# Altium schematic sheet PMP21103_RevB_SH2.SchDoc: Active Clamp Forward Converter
size 431 x 279 mm; Date: Not shown in title block; ApprovedBy: Not shown in title block; CheckedBy: Not shown in title block; Author: Not shown in title block; CompanyName: Not shown in title block; Engineer: Not shown in title block; Organization: Not shown in title block; Address1: Not shown in title block; Address2: Not shown in title block; Address3: Not shown in title block; Address4: Not shown in title block; DocumentNumber: 2; Revision: Use project parameter SCH_Rev; SheetNumber: 2; SheetTotal: 3; PageSetup: Record=PageOptions¦CenterHorizontal=True¦CenterVertical=True¦PrintScale=1.00¦XCorrection=1.00¦YCorrection=1.00¦PrintKind=0¦BorderSize=5000000¦LeftOffset=0¦BottomOffset=0¦Orientation=2¦PaperLength=1000¦PaperWidth=1000¦Scale=100¦PaperSource=15¦PrintQuality=600¦MediaType=1¦DitherType=10¦PaperKind=Letter¦PrintScaleMode=1
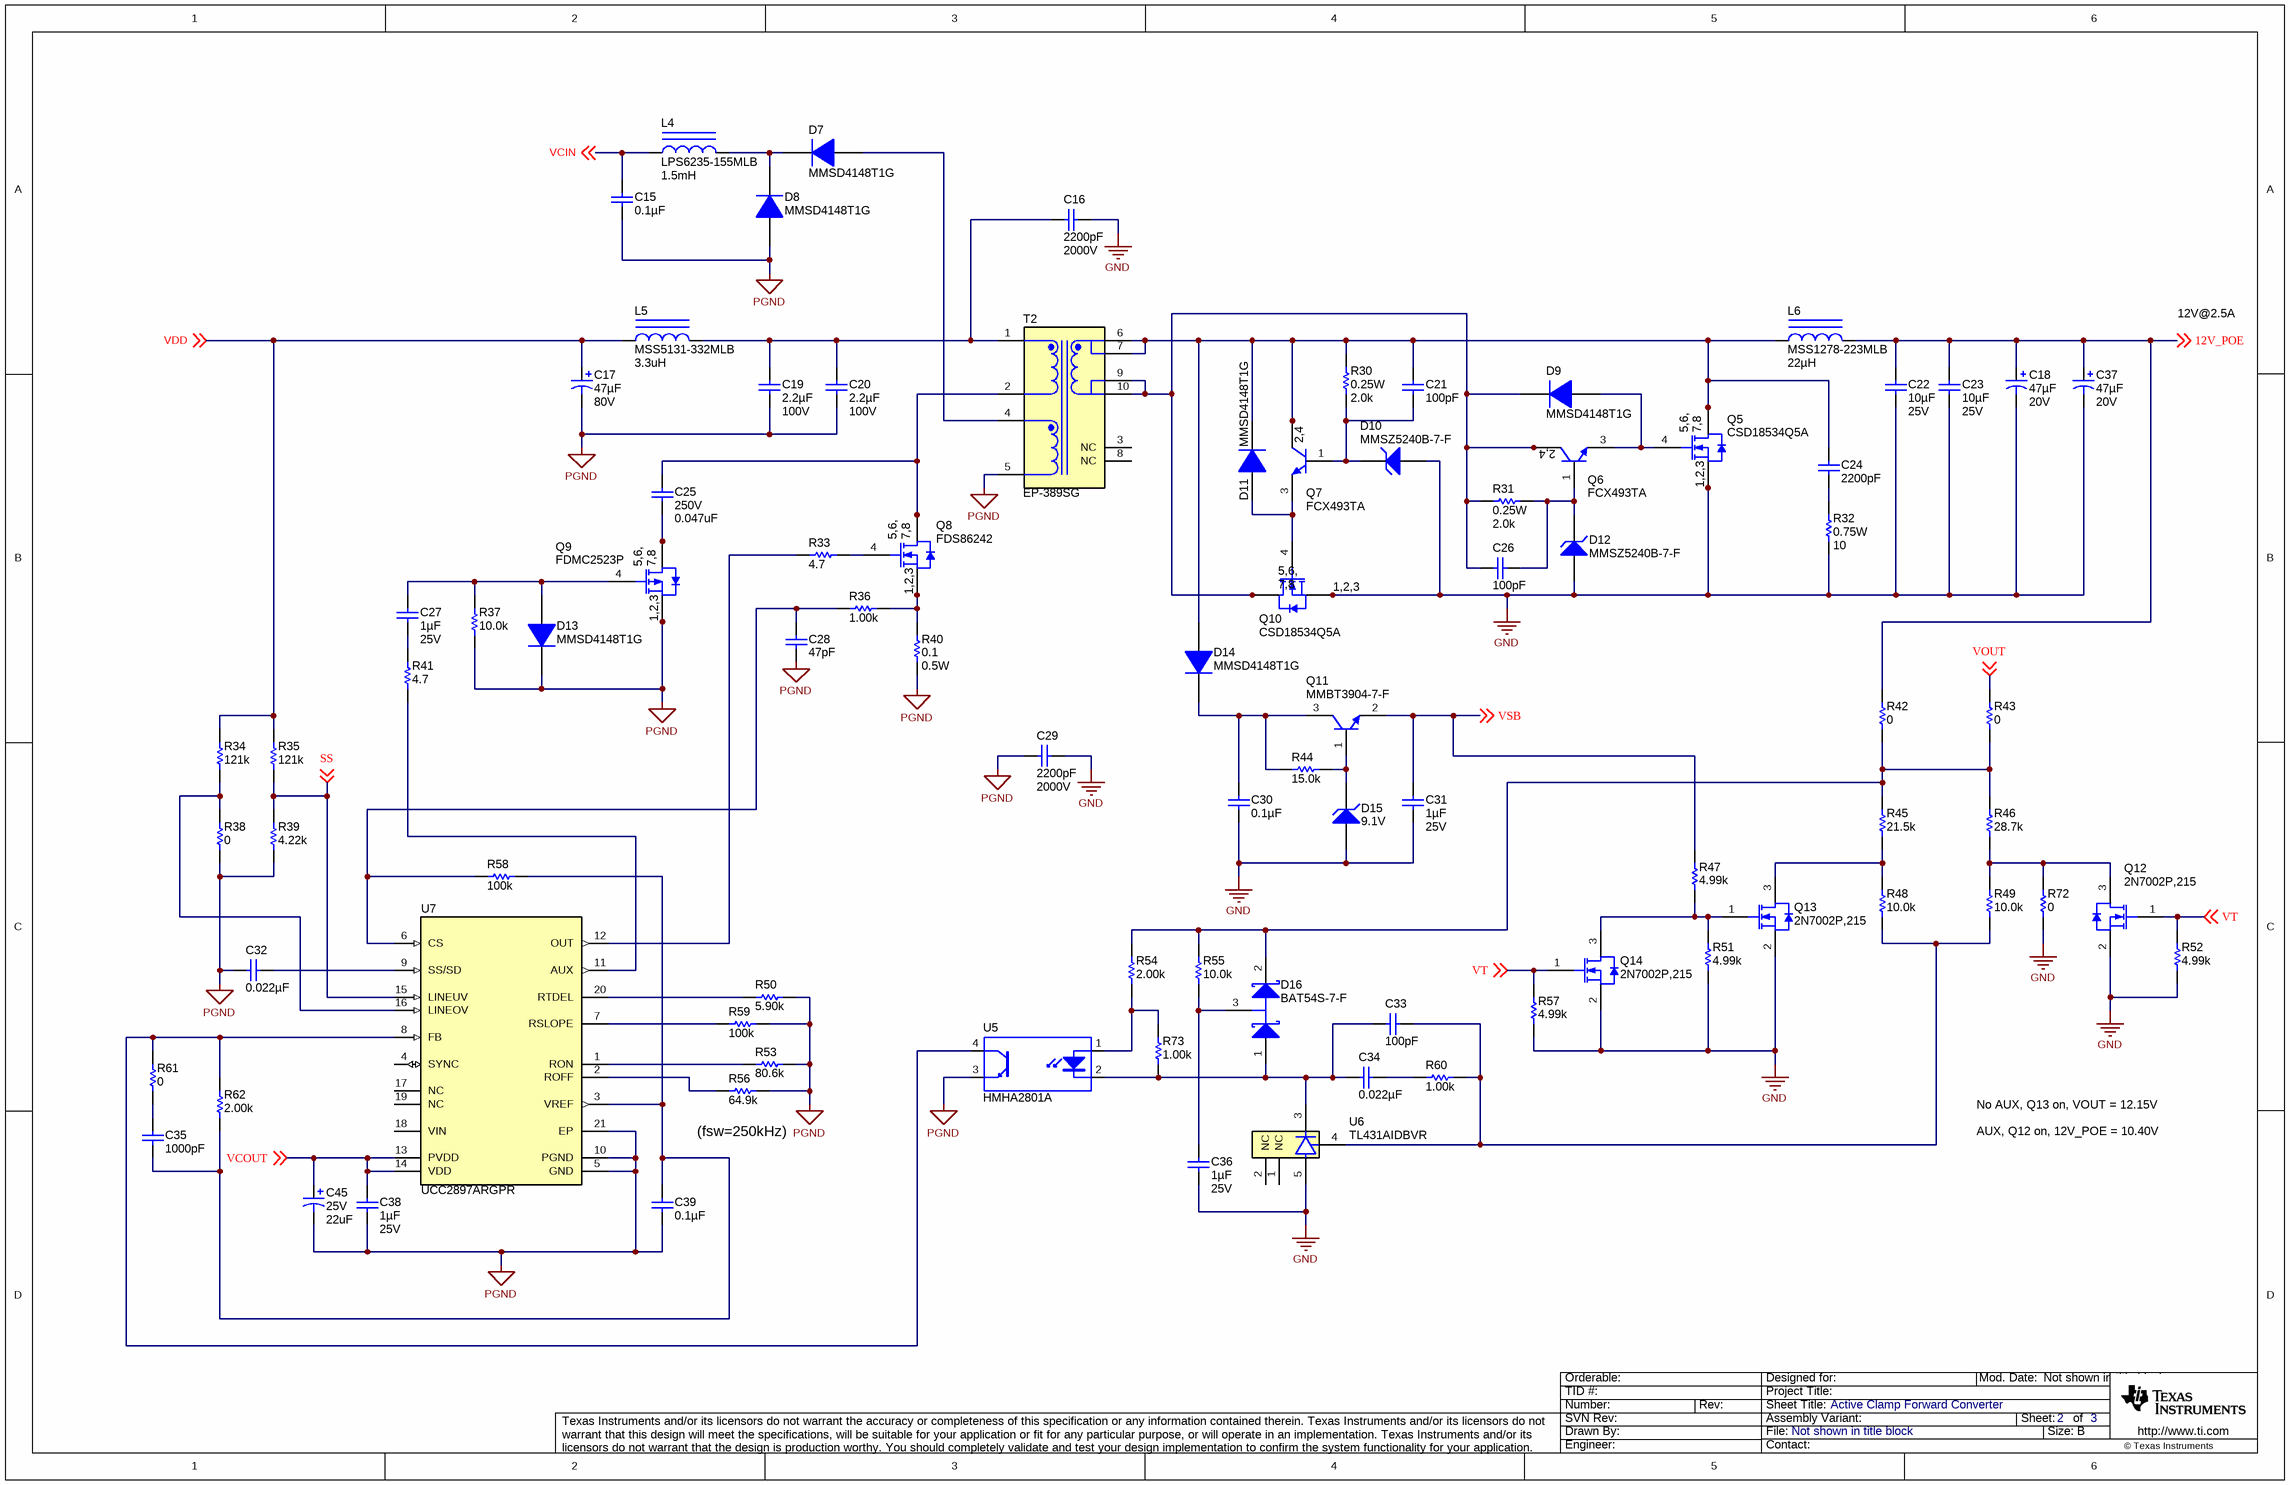
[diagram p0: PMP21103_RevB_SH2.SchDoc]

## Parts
C15  ValueDisplayed: 0.1µF  [0603]  (hidden comment: C1608X7R1H104K080AA)
C16  ValueDisplayed: 2200pF  Value2: 2000V  [1812]  (hidden comment: C4532X7R3D222K130KA)
C17  ValueDisplayed: 47µF  Value2: 80V  [SM_RADIAL_G]  (hidden comment: EEE-FK1K470P)
C18  ValueDisplayed: 47µF  Value2: 20V  [SM_RADIAL_8MM]  (hidden comment: 20SVP47M)
C19  ValueDisplayed: 2.2µF  Value2: 100V  [1210_270]  (hidden comment: GRM32ER72A225KA35L)
C20  ValueDisplayed: 2.2µF  Value2: 100V  [1210_270]  (hidden comment: GRM32ER72A225KA35L)
C21  ValueDisplayed: 100pF  [0603L]  (hidden comment: C1608C0G1H101J080AE)
C22  ValueDisplayed: 10µF  Value2: 25V  [1210_220]  (hidden comment: 885012209028)
C23  ValueDisplayed: 10µF  Value2: 25V  [1210_220]  (hidden comment: 885012209028)
C24  ValueDisplayed: 2200pF  [0603L]  (hidden comment: GRM188R71H222KA01D)
C25  VDC_V: 250V  ValueDisplayed: 0.047uF  [1206_180]  (hidden comment: GRM31CR72E473KW03L)
C26  ValueDisplayed: 100pF  [0603L]  (hidden comment: C1608C0G1H101J080AE)
C27  ValueDisplayed: 1µF  Value2: 25V  [0805L]  (hidden comment: GRM21BR71E105KA99L)
C28  ValueDisplayed: 47pF  [0603L]  (hidden comment: GRM1885C1H470JA01D)
C29  ValueDisplayed: 2200pF  Value2: 2000V  [1812]  (hidden comment: C4532X7R3D222K130KA)
C30  ValueDisplayed: 0.1µF  [0603L]  (hidden comment: C1608X7R1H104K080AA)
C31  ValueDisplayed: 1µF  Value2: 25V  [0805_HV]  (hidden comment: GRM21BR71E105KA99L)
C32  ValueDisplayed: 0.022µF  [0603L]  (hidden comment: GRM188R71H223KA01D)
C33  ValueDisplayed: 100pF  [0603L]  (hidden comment: C1608C0G1H101J080AE)
C34  ValueDisplayed: 0.022µF  [0603L]  (hidden comment: GRM188R71H223KA01D)
C35  ValueDisplayed: 1000pF  [0603]  (hidden comment: GRM188R71H102KA01D)
C36  ValueDisplayed: 1µF  Value2: 25V  [0805_HV]  (hidden comment: GRM21BR71E105KA99L)
C37  ValueDisplayed: 47µF  Value2: 20V  [SM_RADIAL_8MM]  (hidden comment: 20SVP47M)
C38  ValueDisplayed: 1µF  Value2: 25V  [0805L]  (hidden comment: GRM21BR71E105KA99L)
C39  ValueDisplayed: 0.1µF  [0603L]  (hidden comment: C1608X7R1H104K080AA)
C45  VDC_V: 25V  ValueDisplayed: 22uF  [SM_RADIAL_C]  (hidden comment: EEE-FK1E220R)
D7  MMSD4148T1G  [SOD-123]
D8  MMSD4148T1G  [SOD-123]
D9  MMSD4148T1G  [SOD-123]
D10  MMSZ5240B-7-F  [SOD-123]
D11  MMSD4148T1G  [SOD-123]
D12  MMSZ5240B-7-F  [SOD-123]
D13  MMSD4148T1G  [SOD-123]
D14  MMSD4148T1G  [SOD-123]
D15  value 9.1V  [SOD-523]  (hidden comment: BZT52C9V1T-7)
D16  BAT54S-7-F  [SOT-23]
L4  LPS6235-155MLB  ValueDisplayed: 1.5mH  [LPS6235]
L5  MSS5131-332MLB  value 3.3uH  [MSS5131]
L6  MSS1278-223MLB  ValueDisplayed: 22µH  [MSS1278]
Q5  CSD18534Q5A  [DQJ0008A]
Q6  FCX493TA  [SOT-89-3]
Q7  FCX493TA  [SOT-89-3]
Q8  FDS86242  [SOIC-8]
Q9  FDMC2523P  [MLP08S]
Q10  CSD18534Q5A  [DQJ0008A]
Q11  MMBT3904-7-F  [SOT-23]
Q12  2N7002P,215  [SOT-23]
Q13  2N7002P,215  [SOT-23]
Q14  2N7002P,215  [SOT-23]
R30  Value2: 0.25W  ValueDisplayed: 2.0k  [1206L]  (hidden comment: CRCW12062K00JNEA)
R31  Value2: 0.25W  ValueDisplayed: 2.0k  [1206L]  (hidden comment: CRCW12062K00JNEA)
R32  Value2: 0.75W  ValueDisplayed: 10  [2010L]  (hidden comment: CRCW201010R0JNEF)
R33  ValueDisplayed: 4.7  [0603L]  (hidden comment: CRCW06034R70JNEA)
R34  ValueDisplayed: 121k  [0603L]  (hidden comment: CRCW0603121KFKEA)
R35  ValueDisplayed: 121k  [0603L]  (hidden comment: CRCW0603121KFKEA)
R36  ValueDisplayed: 1.00k  [0603]  (hidden comment: CRCW06031K00FKEA)
R37  ValueDisplayed: 10.0k  [0603L]  (hidden comment: CRCW060310K0FKEA)
R38  ValueDisplayed: 0  [0603L]  (hidden comment: CRCW06030000Z0EA)
R39  ValueDisplayed: 4.22k  [0603L]  (hidden comment: CRCW06034K22FKEA)
R40  value 0.1  Value2: 0.5W  [2010L]  (hidden comment: ERJ-L1DKF10CU)
R41  ValueDisplayed: 4.7  [0603L]  (hidden comment: CRCW06034R70JNEA)
R42  ValueDisplayed: 0  [0603L]  (hidden comment: CRCW06030000Z0EA)
R43  ValueDisplayed: 0  [0603L]  (hidden comment: CRCW06030000Z0EA)
R44  ValueDisplayed: 15.0k  [0603]  (hidden comment: CRCW060315K0FKEA)
R45  ValueDisplayed: 21.5k  [0603]  (hidden comment: CRCW060321K5FKEA)
R46  ValueDisplayed: 28.7k  [0603L]  (hidden comment: CRCW060328K7FKEA)
R47  ValueDisplayed: 4.99k  [0603L]  (hidden comment: CRCW06034K99FKEA)
R48  ValueDisplayed: 10.0k  [0603L]  (hidden comment: CRCW060310K0FKEA)
R49  ValueDisplayed: 10.0k  [0603L]  (hidden comment: CRCW060310K0FKEA)
R50  ValueDisplayed: 5.90k  [0603L]  (hidden comment: CRCW06035K90FKEA)
R51  ValueDisplayed: 4.99k  [0603L]  (hidden comment: CRCW06034K99FKEA)
R52  ValueDisplayed: 4.99k  [0603L]  (hidden comment: CRCW06034K99FKEA)
R53  ValueDisplayed: 80.6k  [0603]  (hidden comment: CRCW060380K6FKEA)
R54  ValueDisplayed: 2.00k  [0603L]  (hidden comment: CRCW06032K00FKEA)
R55  ValueDisplayed: 10.0k  [0603L]  (hidden comment: CRCW060310K0FKEA)
R56  ValueDisplayed: 64.9k  [0603]  (hidden comment: CRCW060364K9FKEA)
R57  ValueDisplayed: 4.99k  [0603L]  (hidden comment: CRCW06034K99FKEA)
R58  ValueDisplayed: 100k  [0603L]  (hidden comment: CRCW0603100KFKEA)
R59  ValueDisplayed: 100k  [0603]  (hidden comment: CRCW0603100KFKEA)
R60  ValueDisplayed: 1.00k  [0603L]  (hidden comment: CRCW06031K00FKEA)
R61  ValueDisplayed: 0  [0603L]  (hidden comment: CRCW06030000Z0EA)
R62  ValueDisplayed: 2.00k  [0603L]  (hidden comment: CRCW06032K00FKEA)
R72  ValueDisplayed: 0  [0603L]  (hidden comment: CRCW06030000Z0EA)
R73  ValueDisplayed: 1.00k  [0603L]  (hidden comment: CRCW06031K00FKEA)
T2  EP-389SG  [Mentech_EP-389SG]
U5  HMHA2801A  [MFP04A]
U6  TL431AIDBVR  [DBV0005A_N]
U7  UCC2897ARGPR  [RGP0020D]

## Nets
GND: C16.1 C18.2(-) C22.2 C23.2 C29.1 C30.1 C31.2 C36.2 C37.2(-) D10.2(A) D12.2(A) D15.2(A) Q5.1(S) Q5.2(S) Q5.3(S) Q10.1(S) Q10.2(S) Q10.3(S) Q12.2(S) Q13.2(S) Q14.2(S) R32.1 R51.1 R52.1 R57.1 R72.1 U6.5(A)
PGND: C15.1 C17.2(-) C19.2 C20.2 C28.2 C29.2 C32.2 C38.2 C39.1 C45.2(-) D8.2(A) D13.1(K) Q9.1(S) Q9.2(S) Q9.3(S) R37.1 R38.1 R39.1 R40.1 R50.1 R53.2 R56.2 R59.2 T2.5 U5.3(E) U7.5(GND) U7.10(PGND) U7.21(EP)
12V_POE: C18.1(+) C22.1 C23.1 C37.1(+) L6.2 R42.2 ; off-sheet 12V_POE
SS: R35.1 R39.2 U7.15(LINEUV) ; off-sheet SS
VCIN: C15.2 L4.1 ; off-sheet VCIN
VCOUT: C38.1 C45.1(+) U7.13(PVDD) U7.14(VDD) ; off-sheet VCOUT
VDD: C17.1(+) L5.1 R34.2 R35.2 ; off-sheet VDD
VOUT: R43.2 ; off-sheet VOUT
VSB: C31.1 Q11.2(E) R47.2 ; off-sheet VSB
VT: Q12.1(G) Q14.1(G) R52.2 R57.2 ; off-sheet VT
NetC16_2: C16.2 C19.1 C20.1 L5.2 T2.1
NetC21_1: C21.1 D10.1(K) Q7.1(B) R30.1
NetC21_2: C21.2 C24.1 D11.1(K) D14.2(A) L6.1 Q5.5(D) Q5.6(D) Q5.7(D) Q5.8(D) Q5.9(D) Q7.2(C) Q7.4(C) R30.2 T2.6 T2.7
NetC24_2: C24.2 R32.2
NetC25_1: C25.1 Q8.5(D) Q8.6(D) Q8.7(D) Q8.8(D) T2.2
NetC25_2: C25.2 Q9.5(D) Q9.6(D) Q9.7(D) Q9.8(D)
NetC26_1: C26.1 D9.1(K) Q6.2(C) Q6.4(C) Q10.5(D) Q10.6(D) Q10.7(D) Q10.8(D) Q10.9(D) R31.1 T2.9 T2.10
NetC26_2: C26.2 D12.1(K) Q6.1(B) R31.2
NetC27_1: C27.1 D13.2(A) Q9.4(G) R37.2
NetC27_2: C27.2 R41.2
NetC28_1: C28.1 R36.1 R58.1 U7.6(CS)
NetC30_2: C30.2 D14.1(K) Q11.3(C) R44.2
NetC32_1: C32.1 U7.9(SS/SD)
NetC33_1: C33.1 R48.1 R49.1 R60.1 U6.4(REF)
NetC33_2: C33.2 C34.2 D16.1(A) R73.2 U5.2(K) U6.3(C)
NetC34_1: C34.1 R60.2
NetC35_1: C35.1 R61.1
NetC35_2: C35.2 C39.2 R58.2 R62.2 U7.3(VREF)
NetC36_1: C36.1 D16.3(C) R55.1
NetD7_1: D7.1(K) D8.1(K) L4.2
NetD7_2: D7.2(A) T2.4
NetD9_2: D9.2(A) Q5.4(G) Q6.3(E)
NetD11_2: D11.2(A) Q7.3(E) Q10.4(G)
NetD15_1: D15.1(K) Q11.1(B) R44.1
NetD16_2: D16.2(K) R42.1 R43.1 R45.2 R46.2 R54.1 R55.2
NetQ8_1: Q8.1(S) Q8.2(S) Q8.3(S) R36.2 R40.2
NetQ8_4: Q8.4(G) R33.2
NetQ12_3: Q12.3(D) R46.1 R49.2 R72.2
NetQ13_1: Q13.1(G) Q14.3(D) R47.1 R51.2
NetQ13_3: Q13.3(D) R45.1 R48.2
NetR33_1: R33.1 U7.12(OUT)
NetR34_1: R34.1 R38.2 U7.16(LINEOV)
NetR41_1: R41.1 U7.11(AUX)
NetR50_2: R50.2 U7.20(RTDEL)
NetR53_1: R53.1 U7.1(RON)
NetR54_2: R54.2 R73.1 U5.1(A)
NetR56_1: R56.1 U7.2(ROFF)
NetR59_1: R59.1 U7.7(RSLOPE)
NetR61_2: R61.2 R62.1 U5.4(C) U7.8(FB)

Not connected (* = marked no-connect by the designer): T2 3(NC) 8(NC); U6 1(NC) 2(NC); U7 4(SYNC) 17(NC) 18(VIN) 19(NC)

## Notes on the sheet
- 12V@2.5A
- No AUX, Q13 on, VOUT = 12.15V
- (near R56) (fsw=250kHz)
- AUX, Q12 on, 12V_POE = 10.40V

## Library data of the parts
C15 = C1608X7R1H104K080AA: CAP, CERM, 0.1 µF, 50 V, +/- 10%, X7R, 0603; Manufacturer: TDK; Polarized: N; CompType: Capacitor; Value: 0.1uF; U/M: EA; Cap_F: 0.0000001; Tolerance_%: 10; ESR_ohm: 0.0296; Value1: 0.0296 ohm; VDC_V: 50; Value2: 50V; IRMS_A: 0.97199; TaMin_C: -55; TaMax_C: 125; SizeArea_mm2: 1.28; SizeAreaWB_mm2: 4.68; SizeX_mm: 1.6; SizeY_mm: 0.8; SizeZ_mm: 1; AEC Category: Q200
C16 C29 = C4532X7R3D222K130KA: CAP, CERM, 2200 pF, 2000 V,+/- 10%, X7R, 1812; Manufacturer: TDK; Polarized: N; CompType: Capacitor; Value: 2200pF; U/M: EA; Cap_F: 0.0000000022; Tolerance_%: 10; VDC_V: 2000; TaMin_C: -55; TaMax_C: 125; SizeArea_mm2: 14.4; SizeAreaWB_mm2: 23.1; SizeX_mm: 4.5; SizeY_mm: 3.2; SizeZ_mm: 1.35; AEC Category: Q200; Green_Lifecycle: Active; Green_REACh: Passed
C17 = EEE-FK1K470P: CAP, AL, 47 µF, 80 V, +/- 20%, 0.7 ohm, AEC-Q200 Grade 2, SMD; Manufacturer: Panasonic; Polarized: Y; CompType: Capacitor; Value: 47uF; U/M: EA; Cap_F: 0.000047; Tolerance_%: 20; Value1: 0.7 ohm; VDC_V: 80; ESR_ohm: 0.7; IRMS_A: 0.2; TaMin_C: -55; TaMax_C: 105; Cap_Case: G; AEC Category: Q200; AEC Grade: 2; SizeAreaWB_mm2: 172.2; SizeArea_mm2: 123.6; SizeX_mm: 12; SizeY_mm: 10.3; SizeZ_mm: 10.2
C18 C37 = 20SVP47M: CAP, Aluminum Polymer, 47 µF, 20 V,+/- 20%, 0.045 ohm, 8x10 SMD; Manufacturer: Panasonic; Polarized: Y; CompType: Capacitor; Value: 47uF; U/M: EA; Cap_F: 0.000047; Tolerance_%: 20; ESR_ohm: 0.045; IRMS_A: 1.89; TaMin_C: -55; TaMax_C: 105; Cap_Case: 8.3x8.3x6.9; SizeAreaWB_mm2: 113.3; SizeArea_mm2: 74.7; SizeX_mm: 9; SizeY_mm: 8.3; SizeZ_mm: 10.2; AEC Category: Q200; Green_Lifecycle: Not Set; Green_REACh: Incomplete
C19 C20 = GRM32ER72A225KA35L: CAP, CERM, 2.2 µF, 100 V, +/- 10%, X7R, 1210; Manufacturer: MuRata; Polarized: N; CompType: Capacitor; Value: 2.2uF; U/M: EA; Cap_F: 0.0000022; Tolerance_%: 10; ESR_ohm: 0.007; Value1: 0.007 ohm; VDC_V: 100; IRMS_A: 4.4; TaMin_C: -55; TaMax_C: 125; Cap_Case: 1210; SizeArea_mm2: 8; SizeAreaWB_mm2: 14.7; SizeX_mm: 3.2; SizeY_mm: 2.5; SizeZ_mm: 2.7; AEC Category: Q200
C21 C26 C33 = C1608C0G1H101J080AE: CAP, CERM, 100 pF, 50 V,+/- 5%, C0G/NP0, 0603; Manufacturer: TDK; Polarized: N; CompType: Capacitor; Value: 100pF; U/M: EA; Cap_F: 0.0000000001; Tolerance_%: 5; VDC_V: 50; Value2: 50V; TaMin_C: -55; TaMax_C: 125; Cap_Case: 0603; SizeArea_mm2: 1.28; SizeAreaWB_mm2: 4.68; SizeX_mm: 1.6; SizeY_mm: 0.8; SizeZ_mm: 1; AEC Category: Q200; Green_Lifecycle: Active; Green_REACh: Passed
C22 C23 = 885012209028: CAP, CERM, 10 µF, 25 V,+/- 10%, X7R, 1210; Manufacturer: Wurth Elektronik; Polarized: N; CompType: Capacitor; Value: 10uF; U/M: EA; Cap_F: 0.00001; Tolerance_%: 10; VDC_V: 25; TaMin_C: -55; TaMax_C: 125; Cap_Case: 1210; SizeArea_mm2: 8; SizeAreaWB_mm2: 14.7; SizeX_mm: 3.2; SizeY_mm: 2.5; SizeZ_mm: 2.2; AEC Category: Q200
C24 = GRM188R71H222KA01D: CAP, CERM, 2200 pF, 50 V, +/- 10%, X7R, 0603; Manufacturer: MuRata; Polarized: N; CompType: Capacitor; Value: 2200pF; U/M: EA; Cap_F: 0.0000000022; Tolerance_%: 10; Value1: Unknown; VDC_V: 50; Value2: 50V; TaMin_C: -55; TaMax_C: 125; Cap_Case: 0603; SizeArea_mm2: 1.28; SizeAreaWB_mm2: 4.68; SizeX_mm: 1.6; SizeY_mm: 0.8; SizeZ_mm: 1; AEC Category: Q200
C25 = CMP-0008975-2: CAP, CERM, 0.047 uF, 250 V, +/- 10%, X7R, 1206; Manufacturer: MuRata; TaMin_C: -55°C; Polarized: N; SizeAreaWB_mm2: 10.92; Value1: Unknown; U/M: EA; TaMax_C: 125°C; SizeZ_mm: 1.8; SizeX_mm: 3.2; SizeY_mm: 1.6; Cap_Case: 1206; SizeArea_mm2: 5.12; Cap_F: 47nF; AEC Category: Q200
C27 C31 C36 C38 = GRM21BR71E105KA99L: CAP, CERM, 1 µF, 25 V, +/- 10%, X7R, 0805; Manufacturer: MuRata; Polarized: N; CompType: Capacitor; Value: 1uF; U/M: EA; Cap_F: 0.000001; Tolerance_%: 10; Value1: Unknown; VDC_V: 25; TaMin_C: -55; TaMax_C: 125; Cap_Case: 0805; SizeArea_mm2: 2.5; SizeAreaWB_mm2: 6.75; SizeX_mm: 2; SizeY_mm: 1.25; SizeZ_mm: 1.45; AEC Category: Q200
C28 = GRM1885C1H470JA01D: CAP, CERM, 47 pF, 50 V, +/- 5%, C0G/NP0, 0603; Manufacturer: MuRata; Polarized: N; CompType: Capacitor; Value: 47pF; U/M: EA; Cap_F: 0.000000000047; Tolerance_%: 5; Value1: Unknown; VDC_V: 50; Value2: 50V; TaMin_C: -55; TaMax_C: 125; Cap_Case: 0603; SizeArea_mm2: 1.28; SizeAreaWB_mm2: 4.68; SizeX_mm: 1.6; SizeY_mm: 0.8; SizeZ_mm: 1; AEC Category: Q200
C30 C39 = C1608X7R1H104K080AA: CAP, CERM, 0.1 µF, 50 V, +/- 10%, X7R, 0603; Manufacturer: TDK; Polarized: N; CompType: Capacitor; Value: 0.1uF; U/M: EA; Cap_F: 0.0000001; Tolerance_%: 10; ESR_ohm: 0.0296; Value1: 0.0296 ohm; VDC_V: 50; Value2: 50V; IRMS_A: 0.97199; TaMin_C: -55; TaMax_C: 125; Cap_Case: 0603; SizeArea_mm2: 1.28; SizeAreaWB_mm2: 4.68; SizeX_mm: 1.6; SizeY_mm: 0.8; SizeZ_mm: 1; AEC Category: Q200
C32 C34 = GRM188R71H223KA01D: CAP, CERM, 0.022 µF, 50 V, +/- 10%, X7R, 0603; Manufacturer: MuRata; Polarized: N; CompType: Capacitor; Value: 0.022uF; U/M: EA; Cap_F: 0.000000022; Tolerance_%: 10; Value1: Unknown; VDC_V: 50; Value2: 50V; TaMin_C: -55; TaMax_C: 125; Cap_Case: 0603; SizeArea_mm2: 1.28; SizeAreaWB_mm2: 4.68; SizeX_mm: 1.6; SizeY_mm: 0.8; SizeZ_mm: 1; AEC Category: Q200
C35 = GRM188R71H102KA01D: CAP, CERM, 1000 pF, 50 V,+/- 10%, X7R, 0603; Manufacturer: MuRata; Polarized: N; CompType: Capacitor; Value: 1000pF; U/M: EA; Cap_F: 0.000000001; Tolerance_%: 10; VDC_V: 50; Value2: 50V; TaMin_C: -55; TaMax_C: 125; SizeArea_mm2: 1.28; SizeAreaWB_mm2: 4.68; SizeX_mm: 1.6; SizeY_mm: 0.8; SizeZ_mm: 1; AEC Category: Q200; Green_Lifecycle: Active; Green_REACh: Passed
C45 = CMP-0010713-1: CAP, AL, 22 uF, 25 V, +/- 20%, 0.7 ohm, AEC-Q200 Grade 2, SMD; Manufacturer: Panasonic; TaMin_C: -55°C; ESR_ohm: 7d; Polarized: Y; SizeAreaWB_mm2: 62.05; Value1: 0.7 ohm; U/M: EA; Value: 22uF; TaMax_C: 105°C; SizeZ_mm: 5.4; SizeX_mm: 6.5; SizeY_mm: 5.3; Cap_Case: C; SizeArea_mm2: 34.45; CompType: Capacitor; Cap_F: 22µF; IRMS_A: 1.6dA; AEC Grade: 2; AEC Category: Q200
D7-D9 D11 D13 D14 = MMSD4148T1G: Diode, Switching, 100 V, 0.2 A, SOD-123; Manufacturer: ON Semiconductor; Value: 100V; U/M: EA; Vf_V: 1; Value1: 0.2A; Value2: 1V; Io_A: 0.2; Vr_V: 100; TJmax_C: 150; SizeAreaWB_mm2: 13.095; SizeArea_mm2: 6.545; SizeX_mm: 3.85; SizeY_mm: 1.7; SizeZ_mm: 1.35; AEC Category: Q101
D10 D12 = MMSZ5240B-7-F: Diode, Zener, 10 V, 500 mW, SOD-123; Manufacturer: Diodes Inc.; Value: 10V; U/M: EA; Power_W: 0.5; Vz_V: 10; Value1: 0.5W; RJA_CperW: 350; SymbolCreator: a0412235; SizeAreaWB_mm2: 13.095; SizeArea_mm2: 6.545; SizeX_mm: 3.85; SizeY_mm: 1.7; SizeZ_mm: 1.35; AEC Category: Q101
D15 = BZT52C9V1T-7: Diode, Zener, 9.1 V, 300 mW, SOD-523; Manufacturer: Diodes Inc.; SymbolCreator: a0412235; U/M: EA; Power_W: 0.3; Vz_V: 9.1; Value1: 0.3W; RJA_CperW: 417; SizeAreaWB_mm2: 5.13; SizeArea_mm2: 1.53; SizeX_mm: 1.7; SizeY_mm: 0.9; SizeZ_mm: 0.65; AEC Category: Q101
D16 = BAT54S-7-F: Diode, Schottky, 30 V, 0.2 A, SOT-23; Manufacturer: Diodes Inc.; Value: 30V; U/M: EA; Vf_V: 0.65; Value1: 0.2A; Value2: 0.65V; Io_A: 0.2; Vr_V: 30; TJmax_C: 125; SizeAreaWB_mm2: 14; SizeArea_mm2: 7.5; SizeX_mm: 2.5; SizeY_mm: 3; SizeZ_mm: 1.1; AEC Category: Q101
L4 = LPS6235-155MLB: Inductor, Shielded Drum Core, Ferrite, 1.5 mH, 0.14 A, 4.6 ohm, SMD; Manufacturer: Coilcraft; Value: 1.5mH; Ind_H: 1.5E-3; Imax_A: 0.14; Irms: 0.26A @ 40C rise; Isat: 0.14A @ 30% inductance drop; DCR_ohm: 4.6; Value1: 4.6 ohm; Value2: 0.14A; SizeAreaWB_mm2: 64; SizeArea_mm2: 36; SizeX_mm: 6; SizeZ_mm: 3.5; AEC Category: Q200; Green_Lifecycle: Not Set; Green_REACh: Incomplete
L5 = MSS5131-332MLB: Inductor, Shielded Drum Core, Ferrite, 3.3 µH, 1.73 A, 0.03 ohm, SMD; Manufacturer: Coilcraft; Ind_H: 3.3E-6; ValueDisplayed: 3.3µH; Imax_A: 1.73; Irms: 2.9A @ 40C rise; Isat: 1.73A @ 30% inductance drop; DCR_ohm: 0.03; Value2: 1.73A; SizeAreaWB_mm2: 50.41; SizeArea_mm2: 26.01; SizeX_mm: 5.1; SizeZ_mm: 3.1; AEC Category: Q200
L6 = MSS1278-223MLB: Inductor, Shielded Drum Core, Ferrite, 22 µH, 4 A, 0.04 ohm, SMD; Manufacturer: Coilcraft; Value: 22uH; Ind_H: 22.0E-6; Imax_A: 4; Irms: 4A @ 40C rise; Isat: 7.24A @ 30% inductance drop; DCR_ohm: 0.04; Value2: 4A; SizeAreaWB_mm2: 204.49; SizeArea_mm2: 151.29; SizeX_mm: 12.3; SizeZ_mm: 8.05; AEC Category: Q200; Green_Lifecycle: Not Set; Green_REACh: Incomplete
Q5 Q10 = CSD18534Q5A: MOSFET, N-CH, 60 V, 50 A, DQJ0008A (VSONP-8); Manufacturer: Texas Instruments; Alternate Manufacturer: None; Value: 60V; U/M: EA; ChType: N; VdsMax_V: 60; Value1: 0.0098 ohm; Rdson45_ohm: 0.0098; Value2: 22 nC; QgTyp_nC: 22; Vgs_V: 2.3; IdsMax_A: 50; SizeAreaWB_mm2: 55.2; SizeArea_mm2: 29.4; SizeX_mm: 6; SizeY_mm: 4.9; SizeZ_mm: 1.1; AEC Category: Q101
Q6 Q7 = FCX493TA, Diodes Inc.: Transistor, NPN, 100 V, 1 A, SOT-89; CompType: BJT; PNP: 0; NPN: 1; Vceo_V: 100; Vcesat1_V: 0.6; Value: 100 V; Value1: 1 A; HfeMax: 300; TaMin_C: -65; TaMax_C: 150; U/M: EA; SymbolCreator: a0412235; SizeAreaWB_mm2: 28.05; SizeArea_mm2: 18.45; SizeX_mm: 4.1; SizeY_mm: 4.5; SizeZ_mm: 1.5; AEC Category: Q101; Green_Lifecycle: Active; Green_REACh: Passed
Q8 = FDS86242: MOSFET, N-CH, 150 V, 4.1 A, SOIC-8; Manufacturer: Fairchild Semiconductor; Alternate Manufacturer: None; Value: 150V; U/M: EA; ChType: N; VdsMax_V: 150; Value1: ? ohm; Value2: 8.9 nC; QgTyp_nC: 8.9; Vgs_V: 20; IdsMax_A: 4.1; SizeAreaWB_mm2: 55.131; SizeArea_mm2: 29.351; SizeX_mm: 5.99; SizeY_mm: 4.9; SizeZ_mm: 1.75; AEC Category: Q101
Q9 = FDMC2523P: MOSFET, P-CH, -150 V, -3 A, QFN-8; Manufacturer: Fairchild Semiconductor; Alternate Manufacturer: None; Value: -150V; U/M: EA; ChType: P; Value1: ? ohm; Value2: 6.2 nC; QgTyp_nC: 6.2; Vgs_V: -30; SizeAreaWB_mm2: 18.49; SizeArea_mm2: 10.89; SizeX_mm: 3.3; SizeZ_mm: 0.8; AEC Category: Q101; AEC Qualified: N
Q11 = MMBT3904-7-F, Diodes Inc.: Transistor, NPN, 40 V, 0.2 A, SOT-23; CompType: BJT; PNP: 0; NPN: 1; Vceo_V: 40; Vcesat1_V: 0.2; Value: 40 V; Value1: 0.2 A; HfeMax: 400; TaMin_C: -55; TaMax_C: 150; SizeAreaWB_mm2: 14; SizeArea_mm2: 7.5; SizeX_mm: 2.5; SizeY_mm: 3; SizeZ_mm: 1.1; U/M: EA; AEC Category: Q101
Q12-Q14 = 2N7002P,215: MOSFET, N-CH, 60 V, 0.36 A, SOT-23; Manufacturer: Nexperia; Alternate Manufacturer: None; U/M: EA; ChType: N; Value: 60V; VdsMax_V: 60; Value1: 2 ohm; Rdson45_ohm: 2; Value2: 0.6 nC; QgTyp_nC: 0.6; Vgs_V: 20; IdsMax_A: 0.36; SizeAreaWB_mm2: 14; SizeArea_mm2: 7.5; SizeX_mm: 2.5; SizeY_mm: 3; SizeZ_mm: 1.1; AEC Category: Q101
R30 R31 = CRCW12062K00JNEA: RES, 2.0 k, 5%, 0.25 W, 1206; Manufacturer: Vishay-Dale; CompType: Resistor; Value: 2.0k; Res_ohm: 2000; Value_Code: 2k00; Tolerance_%: 5; Power_W: 0.25; VDC_V: 200; TempCo: 200 ppm/C; EIA_Code: E24; U/M: EA; SizeArea_mm2: 5.12; SizeX_mm: 3.2; SizeY_mm: 1.6; SizeZ_mm: 1.35; AEC Category: Q200
R32 = CRCW201010R0JNEF: RES, 10, 5%, 0.75 W, AEC-Q200 Grade 0, 2010; Manufacturer: Vishay-Dale; CompType: Resistor; Value: 10; Value_Code: 10R0; Tolerance_%: 5; Power_W: 0.75; VDC_V: 400; TempCo: 200 ppm/C; EIA_Code: E24; U/M: EA; SizeArea_mm2: 12.5; SizeY_mm: 2.5; SizeZ_mm: 1.66; AEC Category: Q200; AEC Qualified: Y; AEC Grade: 0
R33 R41 = CRCW06034R70JNEA: RES, 4.7, 5%, 0.1 W, 0603; Manufacturer: Vishay-Dale; CompType: Resistor; Value: 4.7; Value_Code: 4R70; Tolerance_%: 5; Power_W: 0.1; Value2: 0.1W; VDC_V: 75; TempCo: 200 ppm/C; EIA_Code: E24; U/M: EA; SizeArea_mm2: 1.28; SizeX_mm: 1.6; SizeY_mm: 0.8; SizeZ_mm: 1; AEC Category: Q200
R34 R35 = CRCW0603121KFKEA: RES, 121 k, 1%, 0.1 W, 0603; Manufacturer: Vishay-Dale; CompType: Resistor; Value: 121k; Res_ohm: 121000; Tolerance_%: 1; Power_W: 0.1; Value2: 0.1W; VDC_V: 75; TempCo: 100 ppm/C; EIA_Code: E96; U/M: EA; SizeArea_mm2: 1.28; SizeX_mm: 1.6; SizeY_mm: 0.8; AEC Category: Q200; Green_Lifecycle: Active; Green_REACh: Passed
R36 = CRCW06031K00FKEA: RES, 1.00 k, 1%, 0.1 W, 0603; Manufacturer: Vishay-Dale; CompType: Resistor; Value: 1.00k; Res_ohm: 1000; Value_Code: 1k00; Tolerance_%: 1; Power_W: 0.1; Value2: 0.1W; VDC_V: 75; TempCo: 100 ppm/C; EIA_Code: E96; U/M: EA; SizeArea_mm2: 1.28; SizeX_mm: 1.6; SizeY_mm: 0.8; AEC Category: Q200; Green_Lifecycle: Active; Green_REACh: Passed
R37 R55 = CRCW060310K0FKEA: RES, 10.0 k, 1%, 0.1 W, 0603; Manufacturer: Vishay-Dale; CompType: Resistor; Value: 10.0k; Res_ohm: 10000; Value_Code: 10k0; Tolerance_%: 1; Power_W: 0.1; Value2: 0.1W; VDC_V: 75; TempCo: 100 ppm/C; EIA_Code: E96; U/M: EA; SizeArea_mm2: 1.28; SizeX_mm: 1.6; SizeY_mm: 0.8; AEC Category: Q200
R38 R42 R43 R61 R72 = CRCW06030000Z0EA: RES, 0, 5%, 0.1 W, 0603; Manufacturer: Vishay-Dale; CompType: Resistor; Value: 0; Value_Code: 0000; Tolerance_%: 5; Power_W: 0.1; Value2: 0.1W; VDC_V: 75; TempCo: 200 ppm/C; SizeArea_mm2: 1.28; SizeX_mm: 1.6; SizeY_mm: 0.8; SizeZ_mm: 1; EIA_Code: E24; U/M: EA; AEC Category: Q200
R39 = CRCW06034K22FKEA: RES, 4.22 k, 1%, 0.1 W, 0603; Manufacturer: Vishay-Dale; CompType: Resistor; Value: 4.22k; Res_ohm: 4220; Value_Code: 4k22; Tolerance_%: 1; Power_W: 0.1; Value2: 0.1W; VDC_V: 75; TempCo: 100 ppm/C; EIA_Code: E96; U/M: EA; SizeArea_mm2: 1.28; SizeX_mm: 1.6; SizeY_mm: 0.8; AEC Category: Q200; Green_Lifecycle: Active; Green_REACh: Passed
R40 = ERJ-L1DKF10CU: RES, 0.1 ohm, 1%, 0.5W, 2010; Manufacturer: Panasonic; CompType: Resistor; Value_Code: R100; Tolerance_%: 1; Power_W: 0.5; VDC_V: 0; TempCo: 100 ppm/C; EIA_Code: E96; U/M: EA
R44 = CRCW060315K0FKEA: RES, 15.0 k, 1%, 0.1 W, 0603; Manufacturer: Vishay-Dale; CompType: Resistor; Value: 15.0k; Res_ohm: 15000; Value_Code: 15k0; Tolerance_%: 1; Power_W: 0.1; Value2: 0.1W; VDC_V: 75; TempCo: 100 ppm/C; EIA_Code: E96; U/M: EA; SizeArea_mm2: 1.28; SizeX_mm: 1.6; SizeY_mm: 0.8; AEC Category: Q200; Green_Lifecycle: Active; Green_REACh: Passed
R45 = CRCW060321K5FKEA: RES, 21.5 k, 1%, 0.1 W, 0603; Manufacturer: Vishay-Dale; CompType: Resistor; Value: 21.5k; Res_ohm: 21500; Value_Code: 21k5; Tolerance_%: 1; Power_W: 0.1; Value2: 0.1W; VDC_V: 75; TempCo: 100 ppm/C; EIA_Code: E96; U/M: EA; SizeArea_mm2: 1.28; SizeX_mm: 1.6; SizeY_mm: 0.8; AEC Category: Q200; Green_Lifecycle: Active; Green_REACh: Passed
R46 = CRCW060328K7FKEA: RES, 28.7 k, 1%, 0.1 W, 0603; Manufacturer: Vishay-Dale; CompType: Resistor; Value: 28.7k; Res_ohm: 28700; Value_Code: 28k7; Tolerance_%: 1; Power_W: 0.1; Value2: 0.1W; VDC_V: 75; TempCo: 100 ppm/C; SizeArea_mm2: 1.28; SizeX_mm: 1.6; SizeY_mm: 0.8; EIA_Code: E96; U/M: EA; AEC Category: Q200
R47 R51 R52 R57 = CRCW06034K99FKEA: RES, 4.99 k, 1%, 0.1 W, 0603; Manufacturer: Vishay-Dale; CompType: Resistor; Value: 4.99k; Res_ohm: 4990; Value_Code: 4k99; Tolerance_%: 1; Power_W: 0.1; Value2: 0.1W; VDC_V: 75; TempCo: 100 ppm/C; SizeArea_mm2: 1.28; SizeX_mm: 1.6; SizeY_mm: 0.8; EIA_Code: E96; U/M: EA; AEC Category: Q200
R48 R49 = CRCW060310K0FKEA: RES, 10.0 k, 1%, 0.1 W, 0603; Manufacturer: Vishay-Dale; CompType: Resistor; Value: 10.0k; Res_ohm: 10000; Value_Code: 10k0; Tolerance_%: 1; Power_W: 0.1; Value2: 0.1W; VDC_V: 75; TempCo: 100 ppm/C; EIA_Code: E96; U/M: EA; SizeArea_mm2: 1.28; SizeX_mm: 1.6; SizeY_mm: 0.8; AEC Category: Q200; Green_Lifecycle: Active; Green_REACh: Passed
R50 = CRCW06035K90FKEA: RES, 5.90 k, 1%, 0.1 W, 0603; Manufacturer: Vishay-Dale; CompType: Resistor; Value: 5.90k; Res_ohm: 5900; Value_Code: 5k90; Tolerance_%: 1; Power_W: 0.1; Value2: 0.1W; VDC_V: 75; TempCo: 100 ppm/C; EIA_Code: E96; U/M: EA; SizeArea_mm2: 1.28; SizeX_mm: 1.6; SizeY_mm: 0.8; AEC Category: Q200; Green_Lifecycle: Active; Green_REACh: Passed
R53 = CRCW060380K6FKEA: RES, 80.6 k, 1%, 0.1 W, 0603; Manufacturer: Vishay-Dale; CompType: Resistor; Value: 80.6k; Res_ohm: 80600; Value_Code: 80k6; Tolerance_%: 1; Power_W: 0.1; Value2: 0.1W; VDC_V: 75; TempCo: 100 ppm/C; EIA_Code: E96; U/M: EA; SizeArea_mm2: 1.28; SizeX_mm: 1.6; SizeY_mm: 0.8; AEC Category: Q200; Green_Lifecycle: Active; Green_REACh: Passed
R54 R62 = CRCW06032K00FKEA: RES, 2.00 k, 1%, 0.1 W, 0603; Manufacturer: Vishay-Dale; CompType: Resistor; Value: 2.00k; Res_ohm: 2000; Value_Code: 2k00; Tolerance_%: 1; Power_W: 0.1; Value2: 0.1W; VDC_V: 75; TempCo: 100 ppm/C; EIA_Code: E96; U/M: EA; SizeArea_mm2: 1.28; SizeX_mm: 1.6; SizeY_mm: 0.8; AEC Category: Q200; Green_Lifecycle: Active; Green_REACh: Passed
R56 = CRCW060364K9FKEA: RES, 64.9 k, 1%, 0.1 W, 0603; Manufacturer: Vishay-Dale; CompType: Resistor; Value: 64.9k; Res_ohm: 64900; Value_Code: 64k9; Tolerance_%: 1; Power_W: 0.1; Value2: 0.1W; VDC_V: 75; TempCo: 100 ppm/C; EIA_Code: E96; U/M: EA; SizeArea_mm2: 1.28; SizeX_mm: 1.6; SizeY_mm: 0.8; AEC Category: Q200; Green_Lifecycle: Active; Green_REACh: Passed
R58 = CMP-0021990-2: RES, 100 k, 1%, 0.1 W, 0603; Manufacturer: Vishay-Dale; Power_W: 100mW; TempCo: 100 ppm/C; U/M: EA; Value: 100k; EIA_Code: E96; SizeX_mm: 1.6; SizeY_mm: 0.8; SizeZ_mm: 1; Value2: 0.1W; SizeArea_mm2: 1.28; CompType: Resistor; VDC_V: 75V; AEC Category: Q200
R59 = CRCW0603100KFKEA: RES, 100 k, 1%, 0.1 W, 0603; Manufacturer: Vishay-Dale; CompType: Resistor; Value: 100k; Res_ohm: 100000; Tolerance_%: 1; Power_W: 0.1; Value2: 0.1W; VDC_V: 75; TempCo: 100 ppm/C; EIA_Code: E96; U/M: EA; SizeArea_mm2: 1.28; SizeX_mm: 1.6; SizeY_mm: 0.8; AEC Category: Q200; Green_Lifecycle: Active; Green_REACh: Passed
R60 R73 = CRCW06031K00FKEA: RES, 1.00 k, 1%, 0.1 W, 0603; Manufacturer: Vishay-Dale; CompType: Resistor; Value: 1.00k; Res_ohm: 1000; Value_Code: 1k00; Tolerance_%: 1; Power_W: 0.1; Value2: 0.1W; VDC_V: 75; TempCo: 100 ppm/C; EIA_Code: E96; U/M: EA; SizeArea_mm2: 1.28; SizeX_mm: 1.6; SizeY_mm: 0.8; AEC Category: Q200
T2 = CMP-0077243-1: Transformer, 100.5 uH, SMT; Manufacturer: Mentech; SizeAreaWB_mm2: 319.95; SizeArea_mm2: 252.05; AEC Qualified: N; Lp: 100.5; AEC Category: Q200; SizeZ_mm: 12.7; Ind_H: 100.5µH; SizeY_mm: 17.75; Ns1toNp: 0.565; LeakageInd_H: 900nH; Rsec1_ohm: 0.04; DCR_ohm: 1.1d; SizeX_mm: 14.2
U5 = HMHA2801A: Optocoupler, 3.75 kV, 80-160% CTR, SMT; Manufacturer: Fairchild Semiconductor; CTR (Min): 80%; CTR (Max): 160%; Voltage_Isolation_Vrms: 3750V; SizeAreaWB_mm2: 4; SizeArea_mm2: 1
U6 = TL431AIDBVR: Adjustable Precision Shunt Regulator, DBV0005A (SOT-23-5); Alternate Manufacturer: Texas Instruments; Alternate PartNumber: TL431AIDBVT; SymbolCreator: a0411947; CompType: IC; U/M: EA; SizeArea_mm2: 8.12; SizeAreaWB_mm2: 14.82; SizeX_mm: 2.8; SizeY_mm: 2.9; SizeZ_mm: 1.45; Green_Lifecycle: Active; Green_REACh: Passed
U7 = CMP-0031996-2: Advanced Active Clamp PWM Controller with Current Control, -40 to +125 degC, 20-pin QFN (RGP), Green (RoHS & no Sb/Br); Manufacturer: Texas Instruments; Frequency(Max)(kHz): 1000; Regulated Outputs(#): 1; Rating: Catalog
